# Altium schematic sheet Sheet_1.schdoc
size 292 x 205 mm; Device: A_A4; Symbol: A_A4; Name: A_A4; @Project Name: TK021F2699-RGB_转接板_椭圆-24位; REV: 1.0; Date: 2022-07-25; Sheet: 1/1; Draw By: zhouao; Company: NULL Studio; Convert to PCB: yes; Add into BOM: yes; Border: 1; Width: 1150; Height: 807; Region Start: 1; X Region Count: 1; Y Region Count: 1; Title Block Position: 3; Title Block: 1; @Page No: 1; @Page Count: 1; @Schematic Name: TK021F2699-RGB_转接板_16位; @Board Name: TK021F2699-RGB_转接板_16位; @Update Date: 2024-12-10; @Create Time: 12:25:23; @Update Time: 12:25:23; @Page Name: Sheet_1; @Create Date: 2024-12-10
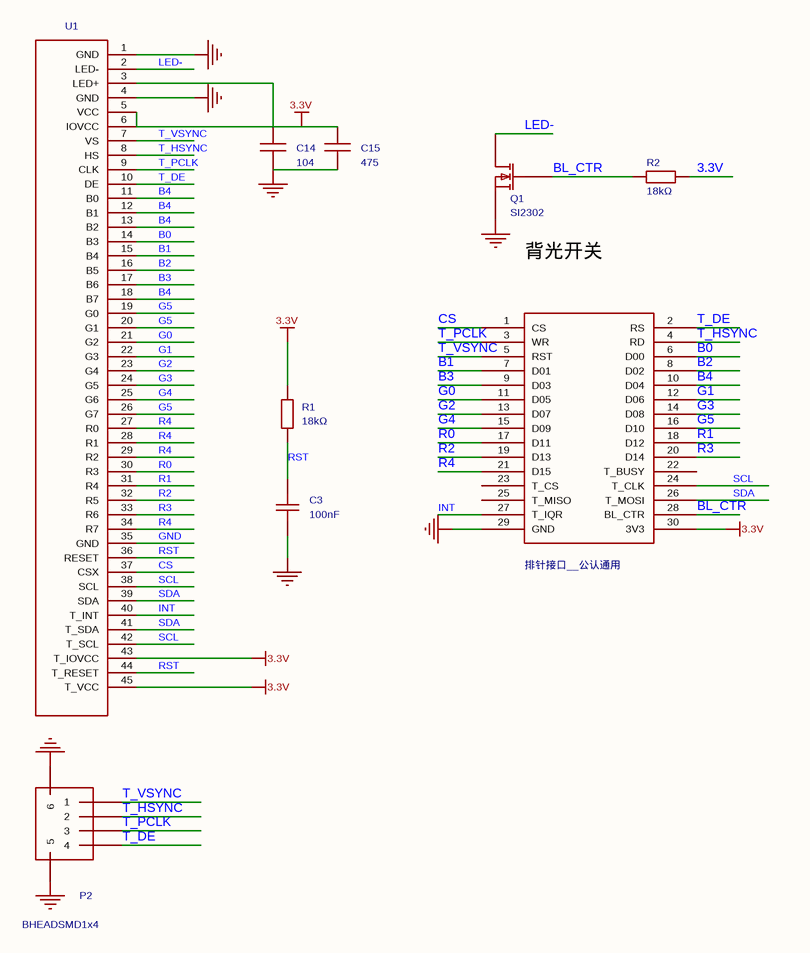
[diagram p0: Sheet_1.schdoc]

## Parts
C3  100nF  [C0603]
C14  104  [C0603-1]
C15  475  [C0603-2]
P2  BHEADSMD1x4  [BHEADSMD1x4]
Q1  SI2302  [SOT23A]
R1  18kΩ  [R0603]
R2  18kΩ  [R0603]
U1  (no value)  [TK043F-45P]
公认通用1  排针接口__公认通用  [P_Head_2x15]

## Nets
3.3V: C14.1 C15.1 R1.2 R2.2 U1.3(LED+) U1.5(VCC) U1.6(IOVCC) U1.43(T_IOVCC) U1.45(T_VCC) 公认通用1.30(3V3)
GND: C3.2 C14.2 C15.2 P2.5 P2.6 Q1.2(S) U1.1(GND) U1.4(GND) U1.35(GND) 公认通用1.29(GND)
B0: U1.14(B3) 公认通用1.6(D00)
B1: U1.15(B4) 公认通用1.7(D01)
B2: U1.16(B5) 公认通用1.8(D02)
B3: U1.17(B6) 公认通用1.9(D03)
B4: U1.11(B0) U1.12(B1) U1.13(B2) U1.18(B7) 公认通用1.10(D04)
BL_CTR: Q1.1(G) R2.1 公认通用1.28(BL_CTR)
CS: U1.37(CSX) 公认通用1.1(CS)
G0: U1.21(G2) 公认通用1.11(D05)
G1: U1.22(G3) 公认通用1.12(D06)
G2: U1.23(G4) 公认通用1.13(D07)
G3: U1.24(G5) 公认通用1.14(D08)
G4: U1.25(G6) 公认通用1.15(D09)
G5: U1.19(G0) U1.20(G1) U1.26(G7) 公认通用1.16(D10)
INT: U1.40(T_INT) 公认通用1.27(T_IQR)
LED-: Q1.3(D) U1.2(LED-)
R0: U1.30(R3) 公认通用1.17(D11)
R1: U1.31(R4) 公认通用1.18(D12)
R2: U1.32(R5) 公认通用1.19(D13)
R3: U1.33(R6) 公认通用1.20(D14)
R4: U1.27(R0) U1.28(R1) U1.29(R2) U1.34(R7) 公认通用1.21(D15)
RST: C3.1 R1.1 U1.36(RESET) U1.44(T_RESET)
SCL: U1.38(SCL) U1.42(T_SCL) 公认通用1.24(T_CLK)
SDA: U1.39(SDA) U1.41(T_SDA) 公认通用1.26(T_MOSI)
T_DE: P2.4 U1.10(DE) 公认通用1.2(RS)
T_HSYNC: P2.2 U1.8(HS) 公认通用1.4(RD)
T_PCLK: P2.3 U1.9(CLK) 公认通用1.3(WR)
T_VSYNC: P2.1 U1.7(VS) 公认通用1.5(RST)

Not connected (* = marked no-connect by the designer): 公认通用1 22(T_BUSY) 23(T_CS) 25(T_MISO)

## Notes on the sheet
- 背光开关

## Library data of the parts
C3 = CC0603KRX7R9BB104: 容值:100nF;精度:±10%;额定电压:50V;材质(温度系数):X7R;; Manufacturer: YAGEO(国巨); Symbol: CC0603KRX7R9BB104_1; AddInBom: yes; ModelId: ac125912035d415993ca9572d50418b1; ModelName: C0603_L1.6-W0.8-H0.8; ModelTransform: 62.992,31.496,0,0,0,0,0,0,0; Tolerance: ±10%; Voltage Rated: 50V; Temperature Coefficient: X7R
C14 = 104: Symbol: cap; Origin Footprint 2: C0402-2; Origin Footprint 3: C0402-3; Origin Footprint 5: C0603-2; Origin Footprint 6: C0603-3; Origin Footprint 7: C0805-1; Origin Footprint 8: C0805-2; Origin Footprint 9: C0805-3; Origin Footprint 10: Case B 3528; Reuse Block: 背光升压输入电源可以用3.3V---5V; Group ID: 1; Channel ID: $1e88; AddInBom: yes
C15 = 475: Symbol: cap; Origin Footprint 2: C0402-1; Origin Footprint 3: C0402-2; Origin Footprint 4: C0402-3; Origin Footprint 5: C0603-1; Origin Footprint 6: C0603-3; Origin Footprint 7: C0805-1; Origin Footprint 8: C0805-2; Origin Footprint 9: C0805-3; Origin Footprint 10: Case B 3528; Reuse Block: 背光升压输入电源可以用3.3V---5V; Group ID: 1; Channel ID: $1e118; AddInBom: yes
P2 = BHEADSMD1x4: AddInBom: yes
Q1 = MOSFET-N: AddInBom: yes; ModelId: 10336ff038a745ff8e8286e7fc8d5503; ModelName: SOT-23-3_L2.9-W1.5-P1.90-LS2.6-BR; ModelTransform: 112.58588000000003,100.93905780575005,42.7049873297486,0,0,0,21.653525000000016,46.25965,0
R1 R2 = 0603WAF1802T5E: 电阻类型:厚膜电阻;阻值:18kΩ;精度:±1%;功率:100mW;最大工作电压:75V;温度系数:±100ppm/℃;; Manufacturer: UNI-ROYAL(厚声); Symbol: 0603WAF1802T5E_1; AddInBom: yes; ModelId: fc143cca1e79419f9cd78b61e9279f080819f05c4eef4c71ace90d822a990e87; ModelTransform: 31.8897,63.7794,0,90,0,0,0,0,0; Tolerance: ±1%; Power(Watts): 100mW; Overload Voltage (Max): 75V
U1 = TK-RGB-45P: Add into BOM: yes; SymbolName: TK021F2699-24
公认通用1 = 排针接口__公认通用: Symbol: LCD_common; AddInBom: yes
